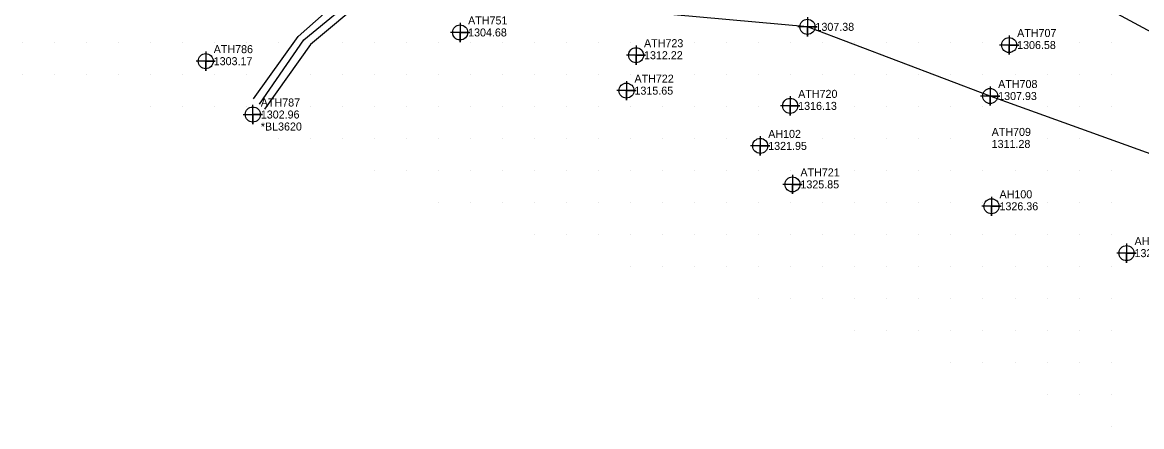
# Model space of a CAD drawing. Extents: x 1234484 to 1235382, y 695050 to 695510.
# Drawn here: x 1234810 to 1235159.5, y 695080 to 695206.2 of the extents above; entities that cross this region are included whole.
import ezdxf

# ---------------------------------------------------------------- set-up
doc = ezdxf.new("R2010")
doc.units = 0
for name, color, linetype in [('Exist DTM Breakline', 7, 'Continuous'), ('Exist DTM Breakline Cogo Elevation', 7, 'Continuous'), ('Exist DTM Breakline Cogo Number', 7, 'Continuous'), ('Exist DTM Breakline Cogo Point CELL', 7, 'Continuous'), ('Exist DTM QL2 LIDAR Elevation Point', 7, 'Continuous'), ('Exist DTM Regular Point CELL', 7, 'Continuous'), ('Exist DTM Regular Point Cogo Elevation', 7, 'Continuous'), ('Exist DTM Regular Point Cogo Number', 7, 'Continuous'), ('Exist Hydro Stream or Body of Water', 7, 'Continuous'), ('Exist Hydro Stream or Body of Water Cogo Comment', 7, 'Continuous'), ('Exist Hydro Stream or Body of Water Cogo Elevation', 7, 'Continuous'), ('Exist Hydro Stream or Body of Water Cogo Number', 7, 'Continuous'), ('Exist Hydro Stream or Body of Water Cogo Point CELL', 7, 'Continuous')]:
    doc.layers.add(name, color=color, linetype=linetype)

msp = doc.modelspace()

# ---------------------------------------------------------------- linework, layer by layer
at = {"layer": 'Exist DTM Breakline'}
for points in [[(1234933.683, 695295.436), (1234929.419, 695292.356), (1234942.895, 695281.98), (1234955.338, 695274.07), (1234960.662, 695260.925), (1234955.311, 695244.507), (1234951.042, 695246.761), (1234943.062, 695238.239), (1234919.786, 695222.886), (1234917.573, 695214.076), (1234899.933, 695199.243), (1234885.657, 695179.089)], [(1234882.128, 695182.331), (1234896.107, 695201.799), (1234912.336, 695216.249), (1234916.953, 695226.235), (1234940.483, 695242.348), (1234951.207, 695257.798), (1234946.446, 695265.278), (1234936.421, 695274.091), (1234919.314, 695287.826), (1234914.388, 695289.733)], [(1235242.403, 695122.486), (1235188.913, 695150.987), (1235163.662, 695164.651), (1235112.238, 695183.191), (1235055.183, 695204.784), (1235005.3, 695209.27), (1234956.312, 695230.116)]]:
    msp.add_lwpolyline(points, dxfattribs=at)
at = {"layer": 'Exist DTM Breakline Cogo Point CELL'}
for points in [[(1235055.183, 695207.784), (1235055.183, 695201.784), (1235055.183, 695204.784), (1235058.183, 695204.784), (1235052.183, 695204.784)], [(1235112.238, 695186.191), (1235112.238, 695180.191), (1235112.238, 695183.191), (1235115.238, 695183.191), (1235109.238, 695183.191)]]:
    msp.add_lwpolyline(points, dxfattribs=at)
for centre in [(1235055.183, 695204.784), (1235112.238, 695183.191)]:
    msp.add_circle(centre, 2.344, dxfattribs=at)
at = {"layer": 'Exist DTM QL2 LIDAR Elevation Point'}
for p, q in [((1234810, 695200), (1234810, 695200)), ((1234820, 695200), (1234820, 695200)), ((1234830, 695200), (1234830, 695200)), ((1234840, 695200), (1234840, 695200)), ((1234850, 695200), (1234850, 695200)), ((1234860, 695200), (1234860, 695200)), ((1234870, 695200), (1234870, 695200)), ((1234880, 695200), (1234880, 695200)), ((1234890, 695200), (1234890, 695200)), ((1234910, 695200), (1234910, 695200)), ((1234920, 695200), (1234920, 695200)), ((1234930, 695200), (1234930, 695200)), ((1234940, 695200), (1234940, 695200)), ((1234950, 695200), (1234950, 695200)), ((1234960, 695200), (1234960, 695200)), ((1234970, 695200), (1234970, 695200)), ((1234980, 695200), (1234980, 695200)), ((1234990, 695200), (1234990, 695200)), ((1235000, 695200), (1235000, 695200)), ((1235010, 695200), (1235010, 695200)), ((1235020, 695200), (1235020, 695200)), ((1235030, 695200), (1235030, 695200)), ((1235040, 695200), (1235040, 695200)), ((1235050, 695200), (1235050, 695200)), ((1235060, 695200), (1235060, 695200)), ((1235070, 695200), (1235070, 695200)), ((1235080, 695200), (1235080, 695200)), ((1235090, 695200), (1235090, 695200)), ((1235100, 695200), (1235100, 695200)), ((1235110, 695200), (1235110, 695200)), ((1235120, 695200), (1235120, 695200)), ((1235130, 695200), (1235130, 695200)), ((1235140, 695200), (1235140, 695200)), ((1235150, 695200), (1235150, 695200)), ((1234810, 695190), (1234810, 695190)), ((1234820, 695190), (1234820, 695190)), ((1234830, 695190), (1234830, 695190)), ((1234840, 695190), (1234840, 695190)), ((1234850, 695190), (1234850, 695190)), ((1234860, 695190), (1234860, 695190)), ((1234870, 695190), (1234870, 695190)), ((1234880, 695190), (1234880, 695190)), ((1234900, 695190), (1234900, 695190)), ((1234910, 695190), (1234910, 695190)), ((1234920, 695190), (1234920, 695190)), ((1234930, 695190), (1234930, 695190)), ((1234940, 695190), (1234940, 695190)), ((1234950, 695190), (1234950, 695190)), ((1234960, 695190), (1234960, 695190)), ((1234970, 695190), (1234970, 695190)), ((1234980, 695190), (1234980, 695190)), ((1234990, 695190), (1234990, 695190)), ((1235000, 695190), (1235000, 695190)), ((1235010, 695190), (1235010, 695190)), ((1235020, 695190), (1235020, 695190)), ((1235030, 695190), (1235030, 695190)), ((1235040, 695190), (1235040, 695190)), ((1235050, 695190), (1235050, 695190)), ((1235060, 695190), (1235060, 695190)), ((1235070, 695190), (1235070, 695190)), ((1235080, 695190), (1235080, 695190)), ((1235090, 695190), (1235090, 695190)), ((1235100, 695190), (1235100, 695190)), ((1235110, 695190), (1235110, 695190)), ((1235120, 695190), (1235120, 695190)), ((1235130, 695190), (1235130, 695190)), ((1235140, 695190), (1235140, 695190)), ((1235150, 695190), (1235150, 695190)), ((1234850, 695180), (1234850, 695180)), ((1234860, 695180), (1234860, 695180)), ((1234870, 695180), (1234870, 695180)), ((1234880, 695180), (1234880, 695180)), ((1234890, 695180), (1234890, 695180)), ((1234900, 695180), (1234900, 695180)), ((1234910, 695180), (1234910, 695180)), ((1234920, 695180), (1234920, 695180)), ((1234930, 695180), (1234930, 695180)), ((1234940, 695180), (1234940, 695180)), ((1234950, 695180), (1234950, 695180)), ((1234960, 695180), (1234960, 695180)), ((1234970, 695180), (1234970, 695180)), ((1234980, 695180), (1234980, 695180)), ((1234990, 695180), (1234990, 695180)), ((1235000, 695180), (1235000, 695180)), ((1235010, 695180), (1235010, 695180)), ((1235020, 695180), (1235020, 695180)), ((1235030, 695180), (1235030, 695180)), ((1235040, 695180), (1235040, 695180)), ((1235060, 695180), (1235060, 695180)), ((1235070, 695180), (1235070, 695180)), ((1235080, 695180), (1235080, 695180)), ((1235090, 695180), (1235090, 695180)), ((1235100, 695180), (1235100, 695180)), ((1235110, 695180), (1235110, 695180)), ((1235130, 695180), (1235130, 695180)), ((1235140, 695180), (1235140, 695180)), ((1235150, 695180), (1235150, 695180)), ((1234890, 695170), (1234890, 695170)), ((1234900, 695170), (1234900, 695170)), ((1234910, 695170), (1234910, 695170)), ((1234920, 695170), (1234920, 695170)), ((1234930, 695170), (1234930, 695170)), ((1234940, 695170), (1234940, 695170)), ((1234950, 695170), (1234950, 695170)), ((1234960, 695170), (1234960, 695170)), ((1234970, 695170), (1234970, 695170)), ((1234980, 695170), (1234980, 695170)), ((1234990, 695170), (1234990, 695170)), ((1235000, 695170), (1235000, 695170)), ((1235010, 695170), (1235010, 695170)), ((1235020, 695170), (1235020, 695170)), ((1235030, 695170), (1235030, 695170)), ((1235040, 695170), (1235040, 695170)), ((1235050, 695170), (1235050, 695170)), ((1235060, 695170), (1235060, 695170)), ((1235070, 695170), (1235070, 695170)), ((1235080, 695170), (1235080, 695170)), ((1235090, 695170), (1235090, 695170)), ((1235100, 695170), (1235100, 695170)), ((1235120, 695170), (1235120, 695170)), ((1235130, 695170), (1235130, 695170)), ((1235140, 695170), (1235140, 695170)), ((1234920, 695160), (1234920, 695160)), ((1234930, 695160), (1234930, 695160)), ((1234940, 695160), (1234940, 695160)), ((1234950, 695160), (1234950, 695160)), ((1234960, 695160), (1234960, 695160)), ((1234970, 695160), (1234970, 695160)), ((1234980, 695160), (1234980, 695160)), ((1234990, 695160), (1234990, 695160)), ((1235000, 695160), (1235000, 695160)), ((1235010, 695160), (1235010, 695160)), ((1235020, 695160), (1235020, 695160)), ((1235030, 695160), (1235030, 695160)), ((1235040, 695160), (1235040, 695160)), ((1235050, 695160), (1235050, 695160)), ((1235060, 695160), (1235060, 695160)), ((1235070, 695160), (1235070, 695160)), ((1235080, 695160), (1235080, 695160)), ((1235090, 695160), (1235090, 695160)), ((1235100, 695160), (1235100, 695160)), ((1235110, 695160), (1235110, 695160)), ((1235120, 695160), (1235120, 695160)), ((1235130, 695160), (1235130, 695160)), ((1235140, 695160), (1235140, 695160)), ((1235150, 695160), (1235150, 695160)), ((1234940, 695150), (1234940, 695150)), ((1234950, 695150), (1234950, 695150)), ((1234960, 695150), (1234960, 695150)), ((1234970, 695150), (1234970, 695150)), ((1234980, 695150), (1234980, 695150)), ((1234990, 695150), (1234990, 695150)), ((1235000, 695150), (1235000, 695150)), ((1235010, 695150), (1235010, 695150)), ((1235020, 695150), (1235020, 695150)), ((1235030, 695150), (1235030, 695150)), ((1235040, 695150), (1235040, 695150)), ((1235050, 695150), (1235050, 695150)), ((1235060, 695150), (1235060, 695150)), ((1235070, 695150), (1235070, 695150)), ((1235080, 695150), (1235080, 695150)), ((1235090, 695150), (1235090, 695150)), ((1235100, 695150), (1235100, 695150)), ((1235110, 695150), (1235110, 695150)), ((1235120, 695150), (1235120, 695150)), ((1235130, 695150), (1235130, 695150)), ((1235140, 695150), (1235140, 695150)), ((1235150, 695150), (1235150, 695150)), ((1234970, 695140), (1234970, 695140)), ((1234980, 695140), (1234980, 695140)), ((1234990, 695140), (1234990, 695140)), ((1235000, 695140), (1235000, 695140)), ((1235010, 695140), (1235010, 695140)), ((1235020, 695140), (1235020, 695140)), ((1235030, 695140), (1235030, 695140)), ((1235040, 695140), (1235040, 695140)), ((1235050, 695140), (1235050, 695140)), ((1235060, 695140), (1235060, 695140)), ((1235070, 695140), (1235070, 695140)), ((1235080, 695140), (1235080, 695140)), ((1235090, 695140), (1235090, 695140)), ((1235100, 695140), (1235100, 695140)), ((1235110, 695140), (1235110, 695140)), ((1235120, 695140), (1235120, 695140)), ((1235130, 695140), (1235130, 695140)), ((1235140, 695140), (1235140, 695140)), ((1235150, 695140), (1235150, 695140)), ((1235000, 695130), (1235000, 695130)), ((1235010, 695130), (1235010, 695130)), ((1235020, 695130), (1235020, 695130)), ((1235030, 695130), (1235030, 695130)), ((1235040, 695130), (1235040, 695130)), ((1235050, 695130), (1235050, 695130)), ((1235060, 695130), (1235060, 695130)), ((1235070, 695130), (1235070, 695130)), ((1235080, 695130), (1235080, 695130)), ((1235090, 695130), (1235090, 695130)), ((1235100, 695130), (1235100, 695130)), ((1235110, 695130), (1235110, 695130)), ((1235120, 695130), (1235120, 695130)), ((1235130, 695130), (1235130, 695130)), ((1235140, 695130), (1235140, 695130)), ((1235150, 695130), (1235150, 695130)), ((1235040, 695120), (1235040, 695120)), ((1235050, 695120), (1235050, 695120)), ((1235060, 695120), (1235060, 695120)), ((1235070, 695120), (1235070, 695120)), ((1235080, 695120), (1235080, 695120)), ((1235090, 695120), (1235090, 695120)), ((1235100, 695120), (1235100, 695120)), ((1235110, 695120), (1235110, 695120)), ((1235120, 695120), (1235120, 695120)), ((1235130, 695120), (1235130, 695120)), ((1235140, 695120), (1235140, 695120)), ((1235150, 695120), (1235150, 695120)), ((1235070, 695110), (1235070, 695110)), ((1235080, 695110), (1235080, 695110)), ((1235090, 695110), (1235090, 695110)), ((1235100, 695110), (1235100, 695110)), ((1235110, 695110), (1235110, 695110)), ((1235120, 695110), (1235120, 695110)), ((1235130, 695110), (1235130, 695110)), ((1235140, 695110), (1235140, 695110)), ((1235150, 695110), (1235150, 695110)), ((1235100, 695100), (1235100, 695100)), ((1235110, 695100), (1235110, 695100)), ((1235120, 695100), (1235120, 695100)), ((1235130, 695100), (1235130, 695100)), ((1235140, 695100), (1235140, 695100)), ((1235150, 695100), (1235150, 695100)), ((1235130, 695090), (1235130, 695090)), ((1235140, 695090), (1235140, 695090)), ((1235150, 695090), (1235150, 695090)), ((1235150, 695080), (1235150, 695080))]:
    msp.add_line(p, q, dxfattribs=at)
at = {"layer": 'Exist DTM Regular Point CELL'}
for points in [[(1234946.704, 695206.035), (1234946.704, 695200.035), (1234946.704, 695203.035), (1234949.704, 695203.035), (1234943.704, 695203.035)], [(1235118.162, 695202.106), (1235118.162, 695196.106), (1235118.162, 695199.106), (1235121.162, 695199.106), (1235115.162, 695199.106)], [(1234867.254, 695197.067), (1234867.254, 695191.067), (1234867.254, 695194.067), (1234870.254, 695194.067), (1234864.254, 695194.067)], [(1235001.645, 695198.928), (1235001.645, 695192.928), (1235001.645, 695195.928), (1235004.645, 695195.928), (1234998.645, 695195.928)], [(1234998.656, 695187.868), (1234998.656, 695181.868), (1234998.656, 695184.868), (1235001.656, 695184.868), (1234995.656, 695184.868)], [(1235049.785, 695183.112), (1235049.785, 695177.112), (1235049.785, 695180.112), (1235052.785, 695180.112), (1235046.785, 695180.112)], [(1235040.425, 695170.618), (1235040.425, 695164.618), (1235040.425, 695167.618), (1235043.425, 695167.618), (1235037.425, 695167.618)], [(1235050.486, 695158.606), (1235050.486, 695152.606), (1235050.486, 695155.606), (1235053.486, 695155.606), (1235047.486, 695155.606)], [(1235112.66, 695151.772), (1235112.66, 695145.772), (1235112.66, 695148.772), (1235115.66, 695148.772), (1235109.66, 695148.772)], [(1235154.826, 695137.145), (1235154.826, 695131.145), (1235154.826, 695134.145), (1235157.826, 695134.145), (1235151.826, 695134.145)]]:
    msp.add_lwpolyline(points, dxfattribs=at)
for centre in [(1234946.704, 695203.035), (1235118.162, 695199.106), (1234867.254, 695194.067), (1235001.645, 695195.928), (1234998.656, 695184.868), (1235049.785, 695180.112), (1235040.425, 695167.618), (1235050.486, 695155.606), (1235112.66, 695148.772), (1235154.826, 695134.145)]:
    msp.add_circle(centre, 2.344, dxfattribs=at)
at = {"layer": 'Exist Hydro Stream or Body of Water'}
for points in [[(1234884.024, 695180.655), (1234897.944, 695200.742), (1234915.887, 695215.628), (1234918.027, 695224.801), (1234941.893, 695240.452), (1234957.27, 695259.086), (1234951.207, 695270.685), (1234942.31, 695277.234), (1234922.587, 695292.008)], [(1235018.754, 695261.568), (1235053.271, 695252.381), (1235081.661, 695240.144), (1235119.353, 695226.521), (1235169.371, 695199.43), (1235188.125, 695189.805), (1235205.75, 695183.352), (1235242.093, 695153.734), (1235263.468, 695141.323)]]:
    msp.add_lwpolyline(points, dxfattribs=at)
at = {"layer": 'Exist Hydro Stream or Body of Water Cogo Point CELL'}
msp.add_lwpolyline([(1234878.964, 695177.417), (1234884.964, 695177.417), (1234881.964, 695177.417), (1234881.964, 695174.417), (1234881.964, 695180.417)], dxfattribs=at)
msp.add_circle((1234881.964, 695177.417), 2.344, dxfattribs=at)

# ---------------------------------------------------------------- texts
at = {"layer": 'Exist DTM Breakline Cogo Elevation'}
for s, p in [('1307.38', (1235057.683, 695203.534)), ('1307.93', (1235114.738, 695181.941))]:
    msp.add_text(s, height=2.5, dxfattribs=at).set_placement(p)
at = {"layer": 'Exist DTM Breakline Cogo Number'}
msp.add_text('ATH708', height=2.5, dxfattribs=at).set_placement((1235114.738, 695185.691))
at = {"layer": 'Exist DTM Regular Point Cogo Elevation'}
for s, p in [('1304.68', (1234949.204, 695201.785)), ('1306.58', (1235120.662, 695197.856)), ('1312.22', (1235004.145, 695194.678)), ('1303.17', (1234869.754, 695192.817)), ('1315.65', (1235001.156, 695183.618)), ('1316.13', (1235052.285, 695178.862)), ('1321.95', (1235042.925, 695166.368)), ('1311.28', (1235112.712, 695166.984)), ('1325.85', (1235052.986, 695154.356)), ('1326.36', (1235115.16, 695147.522)), ('1323.83', (1235157.326, 695132.895))]:
    msp.add_text(s, height=2.5, dxfattribs=at).set_placement(p)
at = {"layer": 'Exist DTM Regular Point Cogo Number'}
for s, p in [('ATH751', (1234949.204, 695205.535)), ('ATH707', (1235120.662, 695201.606)), ('ATH723', (1235004.145, 695198.428)), ('ATH786', (1234869.754, 695196.567)), ('ATH722', (1235001.156, 695187.368)), ('ATH720', (1235052.285, 695182.612)), ('AH102', (1235042.925, 695170.118)), ('ATH709', (1235112.712, 695170.734)), ('ATH721', (1235052.986, 695158.106)), ('AH100', (1235115.16, 695151.272)), ('AH101', (1235157.326, 695136.645))]:
    msp.add_text(s, height=2.5, dxfattribs=at).set_placement(p)
at = {"layer": 'Exist Hydro Stream or Body of Water Cogo Comment'}
msp.add_text('*BL3620', height=2.5, dxfattribs=at).set_placement((1234884.464, 695172.417))
at = {"layer": 'Exist Hydro Stream or Body of Water Cogo Elevation'}
msp.add_text('1302.96', height=2.5, dxfattribs=at).set_placement((1234884.464, 695176.167))
at = {"layer": 'Exist Hydro Stream or Body of Water Cogo Number'}
msp.add_text('ATH787', height=2.5, dxfattribs=at).set_placement((1234884.464, 695179.917))

doc.saveas('drawing.dxf')
